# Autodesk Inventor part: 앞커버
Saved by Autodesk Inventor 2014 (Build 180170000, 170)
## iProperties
Created: 2026-03
Part Number: 앞커버
Material: 일반
Document SubType Name: Modeling
Designer: dg
Density: 1 g/cm^3
Appearance: 기본값
Author: dg
Author: jhkim
Creation Date: 2025-06-27
Sending System: Autodesk Inventor 2026
Preprocessor: ST-DEVELOPER v20.1
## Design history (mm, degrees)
node "앞커버1"
node "솔리드1"
node "기준1"
